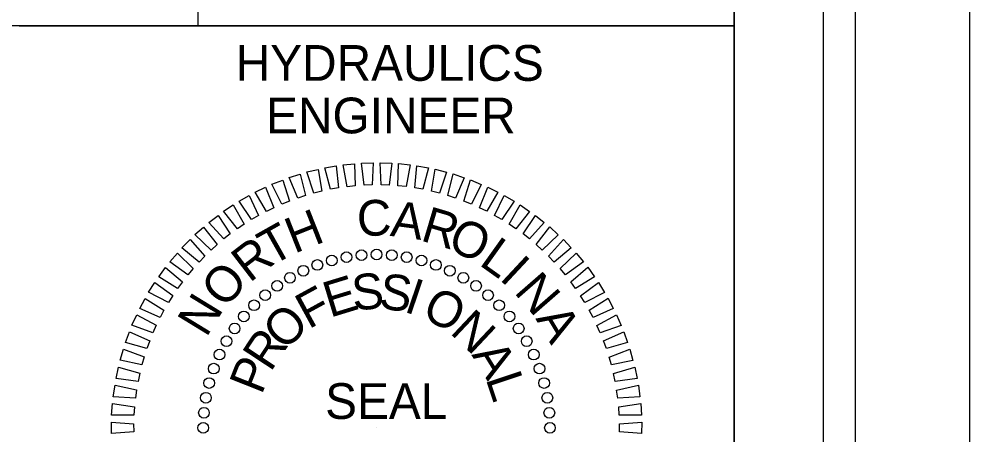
# Model space of a CAD drawing. Extents: x 1632447 to 1634147, y 883210 to 885181.
# Drawn here: x 1634013.8 to 1634146.9, y 884890.3 to 884948.5 of the extents above; entities that cross this region are included whole.
import ezdxf

# ---------------------------------------------------------------- set-up
doc = ezdxf.new("R2010")
doc.units = 0
for name, color, linetype in [('Sheet PE Seal Cell', 7, 'Continuous'), ('Sheet Plot Border Inside CELL', 7, 'Continuous'), ('Sheet Plot Border Outside CELL', 7, 'Continuous'), ('Sheet Profile CELL', 7, 'Continuous'), ('Stewart Plot Border Xerox6279 and LJ5000', 7, 'Continuous')]:
    doc.layers.add(name, color=color, linetype=linetype)

msp = doc.modelspace()

# ---------------------------------------------------------------- linework, layer by layer
at = {"layer": 'Sheet PE Seal Cell'}
msp.add_line((1634063.86, 884891.31), (1634063.86, 884891.31), dxfattribs=at)
for points in [[(1634059.74, 884925.05), (1634059.18, 884928.12), (1634060.79, 884928.26), (1634060.88, 884925.17)], [(1634062.11, 884925.25), (1634061.76, 884928.35), (1634063.38, 884928.38), (1634063.25, 884925.3)], [(1634064.48, 884925.29), (1634064.35, 884928.41), (1634065.97, 884928.33), (1634065.62, 884925.26)], [(1634066.85, 884925.17), (1634066.94, 884928.29), (1634068.54, 884928.09), (1634067.99, 884925.06)], [(1634052.82, 884923.45), (1634051.63, 884926.34), (1634053.18, 884926.81), (1634053.9, 884923.81)], [(1634055.09, 884924.15), (1634054.11, 884927.11), (1634055.68, 884927.47), (1634056.19, 884924.43)], [(1634057.4, 884924.68), (1634056.63, 884927.7), (1634058.22, 884927.95), (1634058.52, 884924.88)], [(1634069.2, 884924.88), (1634069.51, 884927.98), (1634071.1, 884927.67), (1634070.33, 884924.69)], [(1634071.53, 884924.42), (1634072.06, 884927.5), (1634073.62, 884927.08), (1634072.64, 884924.15)], [(1634073.82, 884923.81), (1634074.56, 884926.84), (1634076.09, 884926.31), (1634074.91, 884923.46)], [(1634050.6, 884922.61), (1634049.22, 884925.4), (1634050.73, 884925.98), (1634051.66, 884923.04)], [(1634076.07, 884923.03), (1634077.01, 884926.01), (1634078.5, 884925.37), (1634077.13, 884922.61)], [(1634048.45, 884921.6), (1634046.88, 884924.3), (1634048.34, 884924.98), (1634049.48, 884922.11)], [(1634078.25, 884922.1), (1634079.4, 884925), (1634080.84, 884924.27), (1634079.28, 884921.61)], [(1634046.38, 884920.46), (1634044.62, 884923.03), (1634046.03, 884923.82), (1634047.36, 884921.03)], [(1634080.36, 884921.03), (1634081.71, 884923.84), (1634083.1, 884923.01), (1634081.36, 884920.46)], [(1634044.39, 884919.16), (1634042.45, 884921.61), (1634043.81, 884922.49), (1634045.33, 884919.81)], [(1634082.4, 884919.8), (1634083.94, 884922.51), (1634085.26, 884921.59), (1634083.35, 884919.17)], [(1634042.49, 884917.74), (1634040.39, 884920.04), (1634041.68, 884921.02), (1634043.39, 884918.45)], [(1634084.34, 884918.44), (1634086.07, 884921.04), (1634087.32, 884920.02), (1634085.24, 884917.74)], [(1634040.7, 884916.18), (1634038.44, 884918.34), (1634039.66, 884919.4), (1634041.54, 884916.95)], [(1634086.18, 884916.95), (1634088.09, 884919.42), (1634089.27, 884918.31), (1634087.03, 884916.19)], [(1634039.02, 884914.51), (1634036.62, 884916.5), (1634037.76, 884917.64), (1634039.81, 884915.33)], [(1634087.91, 884915.33), (1634089.99, 884917.66), (1634091.09, 884916.48), (1634088.71, 884914.51)], [(1634037.46, 884912.72), (1634034.93, 884914.54), (1634035.99, 884915.76), (1634038.19, 884913.6)], [(1634089.53, 884913.59), (1634091.76, 884915.77), (1634092.78, 884914.52), (1634090.27, 884912.72)], [(1634036.03, 884910.82), (1634033.38, 884912.46), (1634034.35, 884913.75), (1634036.7, 884911.75)], [(1634091.02, 884911.75), (1634093.4, 884913.77), (1634094.33, 884912.44), (1634091.7, 884910.83)], [(1634034.74, 884908.83), (1634031.97, 884910.28), (1634032.86, 884911.64), (1634035.34, 884909.81)], [(1634092.38, 884909.8), (1634094.9, 884911.65), (1634095.73, 884910.27), (1634092.99, 884908.84)], [(1634033.59, 884906.76), (1634030.73, 884908.01), (1634031.51, 884909.43), (1634034.12, 884907.77)], [(1634093.6, 884907.77), (1634096.24, 884909.44), (1634096.97, 884908), (1634094.15, 884906.76)], [(1634032.58, 884904.61), (1634029.64, 884905.66), (1634030.33, 884907.12), (1634033.04, 884905.66)], [(1634094.68, 884905.65), (1634097.43, 884907.13), (1634098.06, 884905.65), (1634095.15, 884904.61)], [(1634031.73, 884902.4), (1634028.73, 884903.24), (1634029.31, 884904.75), (1634032.12, 884903.47)], [(1634095.6, 884903.47), (1634098.45, 884904.75), (1634098.97, 884903.23), (1634096, 884902.4)], [(1634031.04, 884900.13), (1634027.98, 884900.76), (1634028.45, 884902.3), (1634031.34, 884901.23)], [(1634096.38, 884901.22), (1634099.3, 884902.31), (1634099.72, 884900.75), (1634096.7, 884900.13)], [(1634030.5, 884897.82), (1634027.41, 884898.23), (1634027.77, 884899.81), (1634030.73, 884898.94)], [(1634096.99, 884898.93), (1634099.98, 884899.81), (1634100.29, 884898.22), (1634097.23, 884897.82)], [(1634030.13, 884895.47), (1634027.01, 884895.67), (1634027.27, 884897.27), (1634030.28, 884896.61)], [(1634097.44, 884896.6), (1634100.49, 884897.27), (1634100.68, 884895.67), (1634097.61, 884895.47)], [(1634029.92, 884893.11), (1634026.8, 884893.09), (1634026.94, 884894.7), (1634029.99, 884894.25)], [(1634097.73, 884894.25), (1634100.81, 884894.7), (1634100.9, 884893.09), (1634097.81, 884893.11)], [(1634029.88, 884890.74), (1634026.77, 884890.5), (1634026.79, 884892.12), (1634029.87, 884891.88)], [(1634097.85, 884891.88), (1634100.96, 884892.11), (1634100.93, 884890.5), (1634097.86, 884890.74)]]:
    msp.add_lwpolyline(points, close=True, dxfattribs=at)
for centre in [(1634061.75, 884915.47), (1634063.86, 884915.56), (1634065.98, 884915.47), (1634055.57, 884914.1), (1634057.59, 884914.73), (1634059.65, 884915.19), (1634068.07, 884915.19), (1634070.14, 884914.73), (1634072.16, 884914.1), (1634053.61, 884913.29), (1634074.11, 884913.29), (1634051.74, 884912.31), (1634075.99, 884912.31), (1634049.95, 884911.17), (1634077.77, 884911.17), (1634048.28, 884909.88), (1634079.45, 884909.88), (1634046.72, 884908.46), (1634081.01, 884908.46), (1634045.29, 884906.9), (1634082.44, 884906.9), (1634044, 884905.22), (1634083.73, 884905.22), (1634042.86, 884903.43), (1634084.86, 884903.43), (1634041.89, 884901.56), (1634085.84, 884901.56), (1634041.08, 884899.6), (1634086.65, 884899.6), (1634040.44, 884897.58), (1634087.29, 884897.58), (1634039.98, 884895.52), (1634087.74, 884895.52), (1634039.71, 884893.42), (1634088.02, 884893.42), (1634039.61, 884891.31), (1634088.11, 884891.31)]:
    msp.add_circle(centre, 0.75, dxfattribs=at)
at = {"layer": 'Sheet Plot Border Inside CELL'}
msp.add_lwpolyline([(1634126.36, 884975.16), (1632459.86, 884975.16), (1632459.86, 883920.06), (1634126.36, 883920.06)], close=True, dxfattribs=at)
at = {"layer": 'Sheet Plot Border Outside CELL'}
msp.add_lwpolyline([(1634130.86, 884997.61), (1632446.86, 884997.61), (1632446.86, 883897.61), (1634130.86, 883897.61)], close=True, dxfattribs=at)
at = {"layer": 'Sheet Profile CELL'}
for p, q in [((1634038.86, 884972.56), (1634038.86, 884947.56)), ((1634013.86, 884947.56), (1634113.86, 884947.56)), ((1634113.86, 884947.56), (1634113.86, 884835.06))]:
    msp.add_line(p, q, dxfattribs=at)
for points in [[(1634113.86, 884972.61), (1632613.86, 884972.61), (1632613.86, 883922.61), (1634113.86, 883922.61)], [(1633913.81, 884972.61), (1634113.86, 884972.61), (1634113.86, 884947.56), (1633913.81, 884947.56)]]:
    msp.add_lwpolyline(points, close=True, dxfattribs=at)
at = {"layer": 'Stewart Plot Border Xerox6279 and LJ5000'}
msp.add_lwpolyline([(1632446.86, 883897.61), (1634146.86, 883897.61), (1634146.86, 884997.61), (1632446.86, 884997.61)], close=True, dxfattribs=at)

# ---------------------------------------------------------------- texts
at = {"layer": 'Sheet PE Seal Cell'}
for s, rotation, p in [('C', 1.9618, (1634061.19, 884918.11)), ('A', 352.4568, (1634065.66, 884918.18)), ('H', 21.601, (1634052.34, 884915.65)), ('R', 343.4093, (1634069.86, 884917.56)), ('T', 29.3903, (1634049.15, 884913.87)), ('O', 335.2006, (1634073.55, 884916.44)), ('R', 37.5989, (1634046.08, 884911.53)), ('L', 324.4755, (1634078.05, 884914.2)), ('I', 317.0103, (1634080.91, 884912.16)), ('O', 48.3241, (1634042.63, 884907.87)), ('E', 16.986, (1634057.33, 884906.7)), ('S', 5.2237, (1634060.61, 884907.7)), ('S', 353.2648, (1634064.08, 884908.02)), ('I', 341.3058, (1634067.53, 884907.62)), ('N', 311.0704, (1634082.97, 884910.28)), ('F', 28.6639, (1634054.35, 884905.06)), ('N', 58.5345, (1634040.03, 884903.84)), ('O', 332.5504, (1634069.97, 884906.87)), ('O', 44.4727, (1634050.97, 884901.95)), ('N', 316.7416, (1634073.98, 884904.61)), ('A', 300.8599, (1634086.04, 884906.6)), ('R', 56.5721, (1634049.02, 884899.01)), ('A', 301.6915, (1634077.09, 884901.53)), ('P', 68.3344, (1634047.77, 884895.82)), ('L', 288.3556, (1634079.09, 884898.2))]:
    msp.add_text(s, height=5, rotation=rotation, dxfattribs=at).set_placement(p)
msp.add_text('SEAL', height=5, dxfattribs=at).set_placement((1634056.66, 884892.56))
at = {"layer": 'Sheet Profile CELL'}
for s, p in [('HYDRAULICS', (1634044.15, 884939.86)), ('ENGINEER', (1634048.4, 884932.51))]:
    msp.add_text(s, height=5, dxfattribs=at).set_placement(p)

doc.saveas('drawing.dxf')
